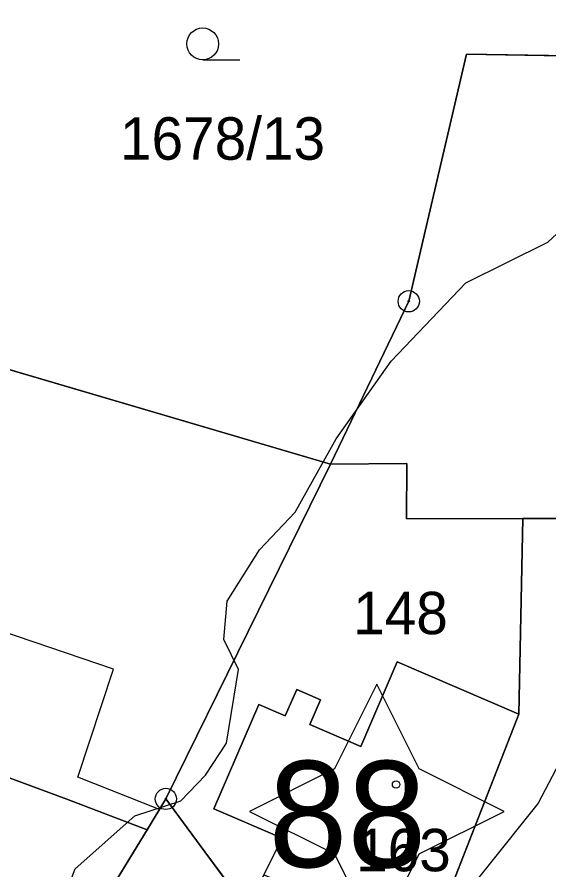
# Model space of a CAD drawing. Extents: x -706130 to -698555, y -971544 to -967260.
# Drawn here: x -704394.67 to -704369.6, y -970233.43 to -970193.24 of the extents above; entities that cross this region are included whole.
import ezdxf

# ---------------------------------------------------------------- set-up
doc = ezdxf.new("R2010")
doc.units = 0
for name, color, linetype in [('_Doplněk budov pro zastavěnost', 7, 'Continuous'), ('Architektonicky cenná stavba S', 7, 'Continuous'), ('BPEJ hranice S', 7, 'Continuous'), ('Docházková izochrona - BUS S', 7, 'Continuous'), ('Docházková izochrona - VLAK N', 7, 'Continuous'), ('KN_Budovy', 7, 'Continuous'), ('KN_Budovy_cisla_domovni', 7, 'Continuous'), ('KN_Hranice_parcel', 7, 'Continuous'), ('KN_Parcelni cisla', 7, 'Continuous'), ('KN_Polygon parcely', 7, 'Continuous'), ('KN_POZEMKY_13_ZASTAVENA PLOCHA', 7, 'Continuous'), ('KN_POZEMKY_14_OSTATNI PLOCHA', 7, 'Continuous'), ('KN_POZEMKY_5_ZAHRADA', 7, 'Continuous'), ('KN_VYUZITI_23_ostatni plocha_manipulacni plocha', 7, 'Continuous'), ('KN_Značky bodu BP', 7, 'Continuous'), ('KN_Značky budov', 7, 'Continuous'), ('KN_Značky kultur', 7, 'Continuous'), ('Záplavové území stanovene S', 7, 'Continuous')]:
    doc.layers.add(name, color=color, linetype=linetype)

msp = doc.modelspace()

# ---------------------------------------------------------------- linework, layer by layer
at = {"layer": '_Doplněk budov pro zastavěnost'}
for p, q in [((-704387.962, -970230.578), (-704391.807, -970229.048)), ((-704388.54, -970231.53), (-704387.962, -970230.578))]:
    msp.add_line(p, q, dxfattribs=at)
for points in [[(-704391.807, -970229.048), (-704390.133, -970223.972), (-704396.19, -970221.903), (-704396.978, -970223.627), (-704396.387, -970223.874), (-704398.008, -970227.989)], [(-704398.008, -970227.989), (-704392.33, -970230.09), (-704388.54, -970231.53)]]:
    msp.add_lwpolyline(points, dxfattribs=at)
at = {"layer": 'Architektonicky cenná stavba S'}
msp.add_lwpolyline([(-704377.717, -970224.668), (-704379.717, -970228.668), (-704383.717, -970230.668), (-704379.717, -970232.668), (-704377.717, -970236.668), (-704375.717, -970232.668), (-704371.717, -970230.668), (-704375.717, -970228.668)], close=True, dxfattribs=at)
at = {"layer": 'BPEJ hranice S'}
msp.add_lwpolyline([(-704367.782, -970225.844), (-704370.102, -970230.283), (-704375.1, -970236.533), (-704375.737, -970237.329), (-704381.252, -970244.227), (-704382.712, -970245.45), (-704383.916, -970246.459), (-704384.724, -970247.136), (-704391.663, -970252.952), (-704398.01, -970258.272), (-704400.038, -970259.971), (-704404.172, -970263.437), (-704405.573, -970264.137), (-704409.891, -970266.297), (-704417.181, -970269.944), (-704427.092, -970270.254), (-704432.635, -970270.254), (-704437.933, -970270.254), (-704450.012, -970264.987)], dxfattribs=at)
at = {"layer": 'Docházková izochrona - BUS S'}
msp.add_arc((-704361.829, -969946.93), 400, 155.51821, 17.33949, dxfattribs=at)
at = {"layer": 'Docházková izochrona - VLAK N'}
msp.add_circle((-704165.451, -969778.767), 800, dxfattribs=at)
at = {"layer": 'KN_Budovy'}
msp.add_lwpolyline([(-704385.39, -970230.55), (-704382.18, -970231.93), (-704383.04, -970233.66), (-704380.79, -970234.56), (-704375.2, -970236.79), (-704371.02, -970226.09), (-704376.75, -970223.62), (-704378.47, -970227.61), (-704380.88, -970226.58), (-704380.37, -970225.41), (-704381.49, -970224.93), (-704382.03, -970226.17), (-704383.27, -970225.63)], close=True, dxfattribs=at)
at = {"layer": 'KN_Hranice_parcel'}
for p, q in [((-704379.9, -970214.31), (-704412.95, -970204.59)), ((-704379.9, -970214.31), (-704387.66, -970230.08)), ((-704371.02, -970226.09), (-704370.83, -970216.86)), ((-704370.83, -970216.86), (-704366.95, -970216.86)), ((-704387.66, -970230.08), (-704388.54, -970231.53)), ((-704388.54, -970231.53), (-704390.64, -970234.97))]:
    msp.add_line(p, q, dxfattribs=at)
for points in [[(-704367.99, -970195.08), (-704373.48, -970194.98), (-704376.21, -970206.63), (-704379.9, -970214.31)], [(-704379.9, -970214.31), (-704376.3, -970214.28), (-704376.32, -970216.88), (-704370.83, -970216.86)], [(-704388.54, -970231.53), (-704392.33, -970230.09), (-704424.7, -970218.11), (-704428.3, -970216.77)], [(-704371.02, -970226.09), (-704376.75, -970223.62), (-704378.47, -970227.61), (-704380.88, -970226.58), (-704380.37, -970225.41), (-704381.49, -970224.93), (-704382.03, -970226.17), (-704383.27, -970225.63), (-704385.39, -970230.55), (-704382.18, -970231.93), (-704383.04, -970233.66), (-704383.83, -970235.26)], [(-704375.38, -970237.42), (-704375.2, -970236.79), (-704371.02, -970226.09)], [(-704387.66, -970230.08), (-704385.82, -970232.57), (-704383.83, -970235.26)]]:
    msp.add_lwpolyline(points, dxfattribs=at)
at = {"layer": 'KN_Polygon parcely'}
for points in [[(-704373.07, -970182.04), (-704381.73, -970177.47), (-704393.35, -970187.6), (-704412.95, -970204.59), (-704379.9, -970214.31), (-704376.21, -970206.63), (-704373.48, -970194.98), (-704367.99, -970195.08), (-704369.51, -970183.33)], [(-704376.32, -970216.88), (-704370.83, -970216.86), (-704366.95, -970216.86), (-704349.06, -970222.09), (-704344.34, -970210.34), (-704345.83, -970208.58), (-704346.44, -970208.42), (-704347.37, -970212.32), (-704354.63, -970210.82), (-704353.47, -970205.19), (-704358.66, -970204.12), (-704358.6, -970203.85), (-704367.89, -970204.12), (-704367.99, -970195.08), (-704373.48, -970194.98), (-704376.21, -970206.63), (-704379.9, -970214.31), (-704376.3, -970214.28)], [(-704379.9, -970214.31), (-704412.95, -970204.59), (-704427.8, -970215.64), (-704428.3, -970216.77), (-704424.7, -970218.11), (-704392.33, -970230.09), (-704388.54, -970231.53), (-704387.66, -970230.08)], [(-704385.82, -970232.57), (-704383.83, -970235.26), (-704383.04, -970233.66), (-704382.18, -970231.93), (-704385.39, -970230.55), (-704383.27, -970225.63), (-704382.03, -970226.17), (-704381.49, -970224.93), (-704380.37, -970225.41), (-704380.88, -970226.58), (-704378.47, -970227.61), (-704376.75, -970223.62), (-704371.02, -970226.09), (-704370.83, -970216.86), (-704376.32, -970216.88), (-704376.3, -970214.28), (-704379.9, -970214.31), (-704387.66, -970230.08)], [(-704390.64, -970234.97), (-704388.54, -970231.53), (-704392.33, -970230.09), (-704424.7, -970218.11), (-704428.3, -970216.77), (-704429.79, -970221.55), (-704430.43, -970233.49), (-704404.13, -970242.29), (-704398.09, -970238.5), (-704394.91, -970239.7), (-704393.46, -970240.6)], [(-704366.78, -970217.54), (-704366.95, -970216.86), (-704370.83, -970216.86), (-704371.02, -970226.09), (-704375.2, -970236.79), (-704375.38, -970237.42), (-704372.16, -970235.59), (-704358.88, -970242.2), (-704356.76, -970243.29), (-704352.93, -970235.65), (-704355.53, -970234.99), (-704366.3, -970232.67), (-704367.39, -970230.26), (-704368.52, -970217.51)], [(-704375.2, -970236.79), (-704371.02, -970226.09), (-704376.75, -970223.62), (-704378.47, -970227.61), (-704380.88, -970226.58), (-704380.37, -970225.41), (-704381.49, -970224.93), (-704382.03, -970226.17), (-704383.27, -970225.63), (-704385.39, -970230.55), (-704382.18, -970231.93), (-704383.04, -970233.66), (-704383.83, -970235.26), (-704375.38, -970237.42)], [(-704380.39, -970248.52), (-704378.59, -970250.89), (-704377.82, -970251.86), (-704377.38, -970250.27), (-704372.07, -970239.22), (-704375.38, -970237.42), (-704383.83, -970235.26), (-704385.82, -970232.57), (-704387.66, -970230.08), (-704388.54, -970231.53), (-704390.64, -970234.97)]]:
    msp.add_lwpolyline(points, close=True, dxfattribs=at)
at = {"layer": 'KN_POZEMKY_13_ZASTAVENA PLOCHA'}
for p, q in [((-704378.47, -970227.61), (-704376.75, -970223.62)), ((-704376.75, -970223.62), (-704371.02, -970226.09)), ((-704382.03, -970226.17), (-704381.49, -970224.93)), ((-704381.49, -970224.93), (-704380.37, -970225.41)), ((-704385.39, -970230.55), (-704383.27, -970225.63)), ((-704383.27, -970225.63), (-704382.03, -970226.17)), ((-704380.37, -970225.41), (-704380.88, -970226.58)), ((-704371.02, -970226.09), (-704375.2, -970236.79)), ((-704380.88, -970226.58), (-704378.47, -970227.61)), ((-704382.18, -970231.93), (-704385.39, -970230.55)), ((-704383.04, -970233.66), (-704382.18, -970231.93))]:
    msp.add_line(p, q, dxfattribs=at)
at = {"layer": 'KN_POZEMKY_14_OSTATNI PLOCHA'}
for p, q in [((-704387.66, -970230.08), (-704379.9, -970214.31)), ((-704379.9, -970214.31), (-704376.3, -970214.28)), ((-704376.3, -970214.28), (-704376.32, -970216.88)), ((-704376.32, -970216.88), (-704370.83, -970216.86)), ((-704371.02, -970226.09), (-704370.83, -970216.86)), ((-704370.83, -970216.86), (-704371.02, -970226.09)), ((-704370.83, -970216.86), (-704366.95, -970216.86)), ((-704376.75, -970223.62), (-704378.47, -970227.61)), ((-704371.02, -970226.09), (-704376.75, -970223.62)), ((-704381.49, -970224.93), (-704382.03, -970226.17)), ((-704380.37, -970225.41), (-704381.49, -970224.93)), ((-704383.27, -970225.63), (-704385.39, -970230.55)), ((-704382.03, -970226.17), (-704383.27, -970225.63)), ((-704380.88, -970226.58), (-704380.37, -970225.41)), ((-704375.2, -970236.79), (-704371.02, -970226.09)), ((-704378.47, -970227.61), (-704380.88, -970226.58)), ((-704385.82, -970232.57), (-704387.66, -970230.08)), ((-704385.39, -970230.55), (-704382.18, -970231.93)), ((-704382.18, -970231.93), (-704383.04, -970233.66)), ((-704383.83, -970235.26), (-704385.82, -970232.57))]:
    msp.add_line(p, q, dxfattribs=at)
at = {"layer": 'KN_POZEMKY_5_ZAHRADA'}
for p, q in [((-704376.21, -970206.63), (-704373.48, -970194.98)), ((-704373.48, -970194.98), (-704376.21, -970206.63)), ((-704373.48, -970194.98), (-704367.99, -970195.08)), ((-704367.99, -970195.08), (-704373.48, -970194.98)), ((-704379.9, -970214.31), (-704412.95, -970204.59)), ((-704412.95, -970204.59), (-704379.9, -970214.31)), ((-704379.9, -970214.31), (-704376.21, -970206.63)), ((-704376.21, -970206.63), (-704379.9, -970214.31)), ((-704379.9, -970214.31), (-704387.66, -970230.08)), ((-704376.3, -970214.28), (-704379.9, -970214.31)), ((-704376.32, -970216.88), (-704376.3, -970214.28)), ((-704370.83, -970216.86), (-704376.32, -970216.88)), ((-704366.95, -970216.86), (-704370.83, -970216.86)), ((-704424.7, -970218.11), (-704392.33, -970230.09)), ((-704392.33, -970230.09), (-704424.7, -970218.11)), ((-704392.33, -970230.09), (-704388.54, -970231.53)), ((-704388.54, -970231.53), (-704392.33, -970230.09)), ((-704388.54, -970231.53), (-704387.66, -970230.08)), ((-704387.66, -970230.08), (-704388.54, -970231.53)), ((-704387.66, -970230.08), (-704385.82, -970232.57)), ((-704388.54, -970231.53), (-704390.64, -970234.97)), ((-704390.64, -970234.97), (-704388.54, -970231.53)), ((-704385.82, -970232.57), (-704383.83, -970235.26))]:
    msp.add_line(p, q, dxfattribs=at)
at = {"layer": 'KN_VYUZITI_23_ostatni plocha_manipulacni plocha'}
for p, q in [((-704387.66, -970230.08), (-704379.9, -970214.31)), ((-704379.9, -970214.31), (-704376.3, -970214.28)), ((-704376.3, -970214.28), (-704376.32, -970216.88)), ((-704376.32, -970216.88), (-704370.83, -970216.86)), ((-704371.02, -970226.09), (-704370.83, -970216.86)), ((-704370.83, -970216.86), (-704371.02, -970226.09)), ((-704370.83, -970216.86), (-704366.95, -970216.86)), ((-704376.75, -970223.62), (-704378.47, -970227.61)), ((-704371.02, -970226.09), (-704376.75, -970223.62)), ((-704381.49, -970224.93), (-704382.03, -970226.17)), ((-704380.37, -970225.41), (-704381.49, -970224.93)), ((-704383.27, -970225.63), (-704385.39, -970230.55)), ((-704382.03, -970226.17), (-704383.27, -970225.63)), ((-704380.88, -970226.58), (-704380.37, -970225.41)), ((-704375.2, -970236.79), (-704371.02, -970226.09)), ((-704378.47, -970227.61), (-704380.88, -970226.58)), ((-704385.82, -970232.57), (-704387.66, -970230.08)), ((-704385.39, -970230.55), (-704382.18, -970231.93)), ((-704382.18, -970231.93), (-704383.04, -970233.66)), ((-704383.83, -970235.26), (-704385.82, -970232.57))]:
    msp.add_line(p, q, dxfattribs=at)
at = {"layer": 'KN_Značky bodu BP'}
for centre, radius in [((-704376.21, -970206.63), 0.5), ((-704376.21, -970206.63), 0.0303), ((-704387.66, -970230.08), 0.5), ((-704387.66, -970230.08), 0.0303)]:
    msp.add_circle(centre, radius, dxfattribs=at)
at = {"layer": 'KN_Značky budov'}
msp.add_circle((-704376.807, -970229.399), 0.175, dxfattribs=at)
at = {"layer": 'KN_Značky kultur'}
msp.add_line((-704385.923, -970195.25), (-704384.173, -970195.25), dxfattribs=at)
msp.add_circle((-704385.923, -970194.5), 0.75, dxfattribs=at)
at = {"layer": 'Záplavové území stanovene S'}
msp.add_lwpolyline([(-704392.625, -970235.167), (-704391.93, -970233.375), (-704389.123, -970230.877), (-704386.956, -970230.165), (-704385.788, -970228.954), (-704384.801, -970227.449), (-704384.236, -970223.986), (-704384.934, -970222.566), (-704384.763, -970220.763), (-704383.239, -970218.346), (-704381.568, -970216.568), (-704379.625, -970213.105), (-704377.043, -970209.457), (-704373.513, -970205.763), (-704369.658, -970203.842), (-704369.001, -970203.249)], dxfattribs=at)

# ---------------------------------------------------------------- texts
at = {"layer": 'KN_Budovy_cisla_domovni'}
msp.add_text('88', height=5, dxfattribs=at).set_placement((-704382.818, -970233.294))
at = {"layer": 'KN_Parcelni cisla'}
for s, p in [('1678/13', (-704389.82, -970199.96)), ('148', (-704378.83, -970222.32)), ('163', (-704378.69, -970233.49))]:
    msp.add_text(s, height=2, dxfattribs=at).set_placement(p)

doc.saveas('drawing.dxf')
